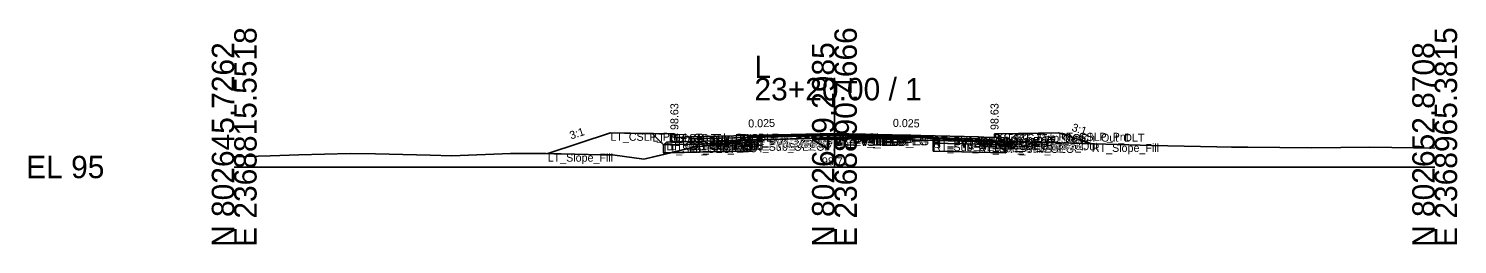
# Model space of a CAD drawing. Extents: x -26 to 8153, y -10 to 9520.
# Drawn here: x 974.3 to 1152.8, y 5490.3 to 5517.3 of the extents above; entities that cross this region are included whole.
import ezdxf

# ---------------------------------------------------------------- set-up
doc = ezdxf.new("R2010")
doc.units = 0
for name, color, linetype in [('Exist CMT Pavement', 7, 'Continuous'), ('Exist Cross Section Cell', 7, 'Continuous'), ('Exist XS Center Line Elevation Label', 7, 'Continuous'), ('Exist XS Ground Line', 7, 'Continuous'), ('Prop CMT Conc Surface', 7, 'Continuous'), ('Prop CMT Concrete Structures', 7, 'Continuous'), ('Prop CMT Pvmt Course 1', 7, 'Continuous'), ('Prop CMT Pvmt Course 1 CG', 7, 'Continuous'), ('Prop CMT Pvmt Course 1 Wedge', 7, 'Continuous'), ('Prop CMT Pvmt Course 2', 7, 'Continuous'), ('Prop CMT Pvmt Course 2 Wedge', 7, 'Continuous'), ('Prop CMT Pvmt Course 3', 7, 'Continuous'), ('Prop CMT Pvmt Course 3 Wedge', 7, 'Continuous'), ('Prop CMT Pvmt Surface', 7, 'Continuous'), ('Prop CMT Pvmt Wedge Surface 1', 7, 'Continuous'), ('Prop CMT Pvmt Wedge Surface 2', 7, 'Continuous'), ('Prop CMT Pvmt Wedge Surface 3', 7, 'Continuous'), ('Prop CMT Shallow Undercut', 7, 'Continuous'), ('Prop CMT Shallow Undercut Boundary', 7, 'Continuous'), ('Prop CMT Slope Grass', 7, 'Continuous'), ('Prop CMT Subgrade Earthwork', 7, 'Continuous'), ('Prop XS Earthwork Shape', 7, 'Continuous'), ('Prop XS Hydro Elevations', 7, 'Continuous'), ('Prop XS SE Text', 7, 'Continuous'), ('Prop XS Side Slope Text', 7, 'Continuous'), ('Prop XS Subgrade Earthwork', 7, 'Continuous'), ('Scratch_Level_2', 7, 'Continuous'), ('Scratch_Level_6', 7, 'Continuous')]:
    doc.layers.add(name, color=color, linetype=linetype)

msp = doc.modelspace()

# ---------------------------------------------------------------- linework, layer by layer
at = {"layer": 'Exist CMT Pavement'}
for p, q in [((1064.48, 5503.38), (1068.19, 5503.49)), ((1068.19, 5503.49), (1074.66, 5503.71)), ((1074.66, 5503.71), (1081.47, 5503.69)), ((1081.47, 5503.69), (1085.22, 5503.68)), ((1085.22, 5503.68), (1086.26, 5503.63)), ((1086.26, 5503.63), (1087.34, 5503.52)), ((1087.34, 5503.52), (1087.35, 5503.52)), ((1087.35, 5503.52), (1087.35, 5503.52))]:
    msp.add_line(p, q, dxfattribs=at)
at = {"layer": 'Exist Cross Section Cell'}
for p, q in [((1075, 5500), (1075, 5511.14)), ((1000, 5500), (1075, 5500)), ((1075, 5500), (1150, 5500))]:
    msp.add_line(p, q, dxfattribs=at)
at = {"layer": 'Exist XS Ground Line'}
for p, q in [((1051.18, 5500.98), (1057.21, 5502.43)), ((1057.21, 5502.43), (1057.51, 5502.5)), ((1057.51, 5502.5), (1058.09, 5502.57)), ((1058.09, 5502.57), (1064.48, 5503.38)), ((1064.48, 5503.38), (1068.19, 5503.49)), ((1068.19, 5503.49), (1074.66, 5503.71)), ((1074.66, 5503.71), (1075, 5503.71)), ((1075, 5503.71), (1081.47, 5503.69)), ((1081.47, 5503.69), (1085.22, 5503.68)), ((1085.22, 5503.68), (1086.26, 5503.63)), ((1086.26, 5503.63), (1087.35, 5503.52)), ((1087.35, 5503.52), (1094.67, 5503.26)), ((1094.67, 5503.26), (1095.12, 5503.26)), ((1095.12, 5503.26), (1104.6, 5502.97)), ((1104.6, 5502.97), (1113.21, 5502.72)), ((1113.21, 5502.72), (1114.61, 5502.67)), ((1114.61, 5502.67), (1122.77, 5502.52)), ((1122.77, 5502.52), (1124.62, 5502.49)), ((1124.62, 5502.49), (1126.66, 5502.47)), ((1126.66, 5502.47), (1134.63, 5502.4)), ((1134.63, 5502.4), (1141.88, 5502.47)), ((1141.88, 5502.47), (1144.64, 5502.44)), ((1144.64, 5502.44), (1150, 5502.35)), ((1000, 5501.28), (1004.48, 5501.39)), ((1004.48, 5501.39), (1008.09, 5501.52)), ((1008.09, 5501.52), (1014.49, 5501.7)), ((1014.49, 5501.7), (1017.65, 5501.64)), ((1017.65, 5501.64), (1024.5, 5501.47)), ((1024.5, 5501.47), (1027.21, 5501.41)), ((1027.21, 5501.41), (1034.51, 5501.71)), ((1034.51, 5501.71), (1038.99, 5501.68)), ((1038.99, 5501.68), (1044.23, 5501.55)), ((1044.23, 5501.55), (1045.84, 5501.53)), ((1045.84, 5501.53), (1046.82, 5501.54)), ((1046.82, 5501.54), (1047.26, 5501.51)), ((1047.26, 5501.51), (1051.18, 5500.98))]:
    msp.add_line(p, q, dxfattribs=at)
at = {"layer": 'Prop CMT Conc Surface'}
for points in [[(1055, 5503.63), (1055, 5504.13), (1054.5, 5504.13)], [(1057, 5503.76), (1055, 5503.63)], [(1093, 5503.76), (1095, 5503.63)], [(1095, 5503.63), (1095, 5504.13), (1095.5, 5504.13)]]:
    msp.add_lwpolyline(points, dxfattribs=at)
at = {"layer": 'Prop CMT Concrete Structures'}
for points in [[(1057, 5503.76), (1055, 5503.63), (1055, 5504.13), (1054.5, 5504.13)], [(1054.5, 5504.13), (1054.5, 5503.11), (1057, 5503.18)], [(1057, 5503.18), (1057, 5503.76)], [(1093, 5503.76), (1095, 5503.63), (1095, 5504.13), (1095.5, 5504.13)], [(1095.5, 5504.13), (1095.5, 5503.11), (1093, 5503.18)], [(1093, 5503.18), (1093, 5503.76)]]:
    msp.add_lwpolyline(points, dxfattribs=at)
at = {"layer": 'Prop CMT Pvmt Course 1'}
for points in [[(1075, 5504.21), (1057, 5503.76)], [(1075, 5503.96), (1075, 5504.21)], [(1075, 5504.21), (1093, 5503.76)], [(1075, 5503.96), (1075, 5504.21)], [(1057, 5503.76), (1057, 5503.51)], [(1057, 5503.51), (1064.48, 5503.7)], [(1064.48, 5503.82), (1075, 5504.08)], [(1064.48, 5503.7), (1064.48, 5503.82)], [(1075, 5504.08), (1075, 5503.96), (1075, 5503.96)], [(1087.35, 5503.78), (1075, 5504.08)], [(1075, 5504.08), (1075, 5503.96), (1075, 5503.96)], [(1087.35, 5503.65), (1087.35, 5503.78)], [(1093, 5503.51), (1087.35, 5503.65)], [(1093, 5503.76), (1093, 5503.51)]]:
    msp.add_lwpolyline(points, dxfattribs=at)
at = {"layer": 'Prop CMT Pvmt Course 1 CG'}
for points in [[(1057, 5503.18), (1054, 5503.1), (1053.66, 5502.76)], [(1053.66, 5502.76), (1057, 5502.85)], [(1057, 5502.85), (1057, 5503.18)], [(1093, 5503.18), (1096, 5503.1), (1096.34, 5502.76)], [(1093, 5502.85), (1093, 5503.18)], [(1096.34, 5502.76), (1093, 5502.85)]]:
    msp.add_lwpolyline(points, dxfattribs=at)
at = {"layer": 'Prop CMT Pvmt Course 1 Wedge'}
for points in [[(1075, 5504.08), (1064.48, 5503.82)], [(1075, 5504.08), (1087.35, 5503.78)]]:
    msp.add_lwpolyline(points, dxfattribs=at)
at = {"layer": 'Prop CMT Pvmt Course 2'}
for points in [[(1064.48, 5503.7), (1057, 5503.51)], [(1057, 5503.51), (1057, 5503.18)], [(1057, 5503.18), (1064.48, 5503.37)], [(1064.48, 5503.37), (1064.48, 5503.7)], [(1087.35, 5503.32), (1087.35, 5503.65)], [(1087.35, 5503.65), (1093, 5503.51)], [(1093, 5503.18), (1087.35, 5503.32)], [(1093, 5503.51), (1093, 5503.18)]]:
    msp.add_lwpolyline(points, dxfattribs=at)
at = {"layer": 'Prop CMT Pvmt Course 2 Wedge'}
for points in [[(1075, 5503.96), (1064.48, 5503.7)], [(1075, 5503.96), (1087.35, 5503.65)]]:
    msp.add_lwpolyline(points, dxfattribs=at)
at = {"layer": 'Prop CMT Pvmt Course 3'}
for points in [[(1064.48, 5503.37), (1057, 5503.18)], [(1057, 5503.18), (1057, 5502.85)], [(1057, 5502.85), (1064.48, 5503.03)], [(1064.48, 5503.03), (1064.48, 5503.37)], [(1087.35, 5503.32), (1093, 5503.18)], [(1087.35, 5502.99), (1087.35, 5503.32)], [(1093, 5502.85), (1087.35, 5502.99)], [(1093, 5503.18), (1093, 5502.85)]]:
    msp.add_lwpolyline(points, dxfattribs=at)
at = {"layer": 'Prop CMT Pvmt Course 3 Wedge'}
for points in [[(1075, 5503.63), (1064.48, 5503.37)], [(1075, 5503.63), (1087.35, 5503.32)]]:
    msp.add_lwpolyline(points, dxfattribs=at)
at = {"layer": 'Prop CMT Pvmt Surface'}
for points in [[(1075, 5504.21), (1057, 5503.76)], [(1075, 5504.21), (1093, 5503.76)]]:
    msp.add_lwpolyline(points, dxfattribs=at)
at = {"layer": 'Prop CMT Pvmt Wedge Surface 1'}
for points in [[(1057, 5503.51), (1057, 5503.76)], [(1064.48, 5503.7), (1057, 5503.51)], [(1075, 5504.08), (1064.48, 5503.82)], [(1064.48, 5503.82), (1064.48, 5503.7)], [(1075, 5504.08), (1087.35, 5503.78)], [(1087.35, 5503.78), (1087.35, 5503.65)], [(1087.35, 5503.65), (1093, 5503.51)], [(1093, 5503.51), (1093, 5503.76)]]:
    msp.add_lwpolyline(points, dxfattribs=at)
at = {"layer": 'Prop CMT Pvmt Wedge Surface 2'}
for points in [[(1075, 5503.96), (1057, 5503.51)], [(1057, 5503.51), (1057, 5503.76)], [(1075, 5503.96), (1093, 5503.51)], [(1093, 5503.51), (1093, 5503.76)]]:
    msp.add_lwpolyline(points, dxfattribs=at)
at = {"layer": 'Prop CMT Pvmt Wedge Surface 3'}
for points in [[(1057, 5503.18), (1057, 5503.76)], [(1075, 5503.63), (1057, 5503.18)], [(1075, 5503.63), (1093, 5503.18)], [(1093, 5503.18), (1093, 5503.76)]]:
    msp.add_lwpolyline(points, dxfattribs=at)
at = {"layer": 'Prop CMT Shallow Undercut'}
for p, q in [((1087.35, 5502.99), (1087.35, 5501.99)), ((1096.34, 5502.76), (1087.35, 5502.99)), ((1096.34, 5501.76), (1096.34, 5502.76)), ((1087.35, 5501.99), (1096.34, 5501.76))]:
    msp.add_line(p, q, dxfattribs=at)
msp.add_lwpolyline([(1061.1, 5502.95), (1064.48, 5503.03), (1064.48, 5502.03), (1054.54, 5501.78), (1057.21, 5502.43), (1057.51, 5502.5), (1058.09, 5502.57)], close=True, dxfattribs=at)
at = {"layer": 'Prop CMT Shallow Undercut Boundary'}
for p, q in [((1053.66, 5502.76), (1064.48, 5503.03)), ((1053.66, 5502.76), (1053.66, 5501.76)), ((1064.48, 5503.03), (1064.48, 5502.03)), ((1087.35, 5502.99), (1087.35, 5501.99)), ((1087.35, 5502.99), (1096.34, 5502.76)), ((1096.34, 5502.76), (1096.34, 5501.76)), ((1064.48, 5502.03), (1053.66, 5501.76)), ((1087.35, 5501.99), (1096.34, 5501.76))]:
    msp.add_line(p, q, dxfattribs=at)
at = {"layer": 'Prop CMT Slope Grass'}
for points in [[(1054.5, 5504.13), (1047, 5504.28), (1039.17, 5501.67)], [(1095.5, 5504.13), (1103, 5504.28), (1107.16, 5502.89)]]:
    msp.add_lwpolyline(points, dxfattribs=at)
at = {"layer": 'Prop CMT Subgrade Earthwork'}
for points in [[(1057, 5502.85), (1053.66, 5502.76), (1052.25, 5504.17)], [(1093, 5502.85), (1096.34, 5502.76), (1097.75, 5504.17)], [(1064.48, 5503.03), (1057, 5502.85)], [(1064.48, 5503.03), (1064.5, 5503.38)], [(1087.35, 5502.99), (1087.34, 5503.52)], [(1087.35, 5502.99), (1093, 5502.85)]]:
    msp.add_lwpolyline(points, dxfattribs=at)
at = {"layer": 'Prop XS Earthwork Shape'}
for points in [[(1046.82, 5501.54), (1047.26, 5501.51), (1051.18, 5500.98), (1054.54, 5501.78), (1053.66, 5501.76), (1053.66, 5502.76), (1052.25, 5504.17), (1047, 5504.28), (1039.17, 5501.67), (1044.23, 5501.55), (1045.84, 5501.53)], [(1104.6, 5502.97), (1107.16, 5502.89), (1103, 5504.28), (1097.75, 5504.17), (1096.78, 5503.21)], [(1057.21, 5502.43), (1057.51, 5502.5), (1058.09, 5502.57), (1061.1, 5502.95), (1057, 5502.85), (1053.66, 5502.76), (1053.66, 5501.76), (1054.54, 5501.78)], [(1057.21, 5502.43), (1057.51, 5502.5), (1058.09, 5502.57), (1061.1, 5502.95), (1064.48, 5503.03), (1064.48, 5502.03), (1054.54, 5501.78)], [(1061.1, 5502.95), (1064.48, 5503.38), (1064.5, 5503.38), (1064.48, 5503.03)], [(1093, 5502.85), (1096.34, 5502.76), (1096.78, 5503.21), (1095.12, 5503.26), (1094.67, 5503.26), (1087.35, 5503.52), (1087.34, 5503.52), (1087.35, 5502.99)], [(1093, 5502.85), (1096.34, 5502.76), (1096.34, 5501.76), (1087.35, 5501.99), (1087.35, 5502.99)]]:
    msp.add_lwpolyline(points, close=True, dxfattribs=at)
at = {"layer": 'Prop XS Subgrade Earthwork'}
for p, q in [((1053.66, 5502.76), (1064.48, 5503.03)), ((1096.34, 5502.76), (1087.35, 5502.99))]:
    msp.add_line(p, q, dxfattribs=at)
at = {"layer": 'Scratch_Level_6'}
for p, q in [((1087.35, 5502.99), (1087.35, 5501.99)), ((1096.34, 5502.76), (1087.35, 5502.99)), ((1096.34, 5501.76), (1096.34, 5502.76)), ((1087.35, 5501.99), (1096.34, 5501.76))]:
    msp.add_line(p, q, dxfattribs=at)
msp.add_lwpolyline([(1061.1, 5502.95), (1064.48, 5503.03), (1064.48, 5502.03), (1054.54, 5501.78), (1057.21, 5502.43), (1057.51, 5502.5), (1058.09, 5502.57)], close=True, dxfattribs=at)

# ---------------------------------------------------------------- texts
at = {"layer": 'Exist Cross Section Cell'}
for s, p in [('E 2368815.5518', (1002.8, 5490)), ('E 2368890.4666', (1077.8, 5490)), ('E 2368965.3815', (1152.8, 5490)), ('N 802645.7262', (1000, 5490)), ('N 802649.2985', (1075, 5490)), ('N 802652.8708', (1150, 5490))]:
    msp.add_text(s, height=2.8, rotation=90, dxfattribs=at).set_placement(p)
for s, p in [('L', (1065, 5511.14)), ('23+20.00 / 1', (1065, 5508.34)), ('EL 95', (974, 5498.6))]:
    msp.add_text(s, height=2.8, dxfattribs=at).set_placement(p)
at = {"layer": 'Exist XS Center Line Elevation Label'}
msp.add_text('98.71', height=1, dxfattribs=at).set_placement((1073.43, 5500.21))
at = {"layer": 'Prop XS Hydro Elevations'}
for p in [(1055.5, 5504.63), (1095.5, 5504.63)]:
    msp.add_text('98.63', height=1, rotation=90, dxfattribs=at).set_placement(p)
at = {"layer": 'Prop XS SE Text'}
for rotation, p in [(1.4321, (1064.24, 5504.94)), (358.5679, (1082.29, 5505.03))]:
    msp.add_text('0.025', height=1, rotation=rotation, dxfattribs=at).set_placement(p)
at = {"layer": 'Prop XS Side Slope Text'}
for rotation, p in [(18.4349, (1042.1, 5503.44)), (341.5651, (1104.57, 5504.55))]:
    msp.add_text('3:1', height=1, rotation=rotation, dxfattribs=at).set_placement(p)
at = {"layer": 'Scratch_Level_2'}
for s, p in [('LT_CSLP_Pnt', (1047, 5503.28)), ('LT_Sub_Trench_Out_DLT', (1052.25, 5503.17)), ('PV1_PGL', (1075, 5503.21)), ('RT_Sub_Trench_Out_DLT', (1097.75, 5503.17)), ('RT_CSLP_Pnt', (1103, 5503.28)), ('LT_Sub_OEOP', (1053.66, 5501.76)), ('LT_CG1_Shelf_Out', (1054, 5502.1)), ('LT_CG_Top_BOC', (1054.5, 5503.13)), ('LT_CG_Bot_BOC', (1054.5, 5502.11)), ('LT_CG_Top_Face', (1055, 5503.13)), ('LT_CG_Top_Gut', (1055, 5502.63)), ('LT_PV1_OEOT', (1057, 5502.76)), ('LT_PV2_OEOT', (1057, 5502.51)), ('LT_PV3_OEOT', (1057, 5502.18)), ('LT_CG_Bot_IE', (1057, 5502.18)), ('LT_Sub_OEOT', (1057, 5501.85)), ('LT_PV1_OEEOP', (1064.48, 5502.82)), ('LT_PV2_OEEOP', (1064.48, 5502.7)), ('LT_PV_OEEOP_EG', (1064.48, 5502.38)), ('LT_PV3_OEEOP', (1064.48, 5502.37)), ('LT_Sub_OEEOP', (1064.48, 5502.03)), ('LT_PV_Sub_Tie_Out', (1064.5, 5502.38)), ('RT_PV1_IEEOP', (1075, 5503.08)), ('LT_PV1_IEEOP', (1075, 5503.08)), ('RT_PV2_IEEOP', (1075, 5502.96)), ('LT_PV2_IEEOP', (1075, 5502.96)), ('PV2_PGL', (1075, 5502.96)), ('RT_PV_IEEOP_EG', (1075, 5502.71)), ('LT_PV_IEEOP_EG', (1075, 5502.71)), ('RT_PV3_IEEOP', (1075, 5502.63)), ('LT_PV3_IEEOP', (1075, 5502.63)), ('RT_PV_Sub_Tie_Out', (1087.34, 5502.52)), ('RT_PV1_OEEOP', (1087.35, 5502.78)), ('RT_PV2_OEEOP', (1087.35, 5502.65)), ('RT_PV_OEEOP_EG', (1087.35, 5502.52)), ('RT_PV3_OEEOP', (1087.35, 5502.32)), ('RT_Sub_OEEOP', (1087.35, 5501.99)), ('RT_PV1_OEOT', (1093, 5502.76)), ('RT_PV2_OEOT', (1093, 5502.51)), ('RT_PV3_OEOT', (1093, 5502.18)), ('RT_CG_Bot_IE', (1093, 5502.18)), ('RT_Sub_OEOT', (1093, 5501.85)), ('RT_CG_Top_Face', (1095, 5503.13)), ('RT_CG_Top_Gut', (1095, 5502.63)), ('RT_CG_Top_BOC', (1095.5, 5503.13)), ('RT_CG_Bot_BOC', (1095.5, 5502.11)), ('RT_CG1_Shelf_Out', (1096, 5502.1)), ('RT_Sub_OEOP', (1096.34, 5501.76)), ('RT_Slope_Fill', (1107.16, 5501.89)), ('LT_Slope_Fill', (1039.17, 5500.67))]:
    msp.add_text(s, height=1, dxfattribs=at).set_placement(p)

doc.saveas('drawing.dxf')
